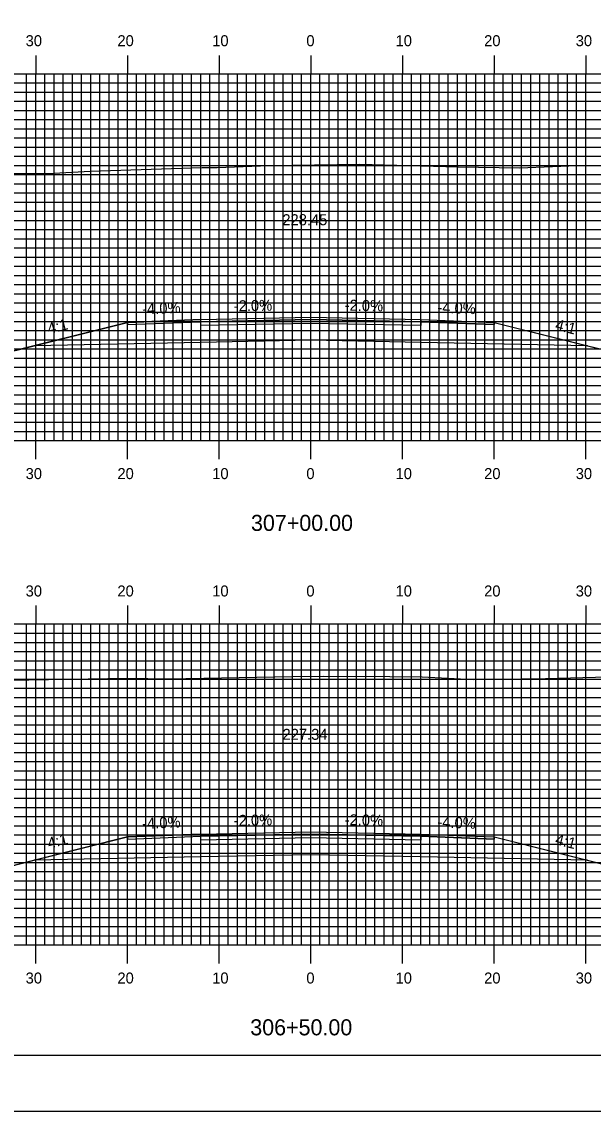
# Model space of a CAD drawing. Extents: x 1817276 to 1817620, y 442591 to 442811.
# Drawn here: x 1817410.6 to 1817472.9, y 442590.5 to 442709.3 of the extents above; entities that cross this region are included whole.
import ezdxf

# ---------------------------------------------------------------- set-up
doc = ezdxf.new("R2010")
doc.units = 0
for name, color, linetype in [('ANNOTATION', 7, 'Continuous'), ('BORDER', 7, 'Continuous'), ('D_Roadway_Centerline', 7, 'Continuous'), ('D_Roadway_Centerline_Text', 7, 'Continuous'), ('D_Roadway_Edge_Shoulder', 7, 'Continuous'), ('D_Roadway_Edge_TW', 7, 'Continuous'), ('D_Roadway_Pavement', 7, 'Continuous'), ('D_Roadway_SlopeLines', 7, 'Continuous'), ('D_Roadway_SubGrade', 7, 'Continuous'), ('H_V ANNOTATION', 7, 'Continuous'), ('MAJOR', 7, 'Continuous'), ('MINOR', 7, 'Continuous'), ('PLOT BOUNDARY', 7, 'Continuous'), ('S_Roadway_Centerline', 7, 'Continuous')]:
    doc.layers.add(name, color=color, linetype=linetype)

msp = doc.modelspace()

# ---------------------------------------------------------------- linework, layer by layer
at = {"layer": 'BORDER'}
msp.add_lwpolyline([(1817292.5, 442596.67), (1817612.5, 442596.67), (1817612.5, 442806.67), (1817292.5, 442806.67)], close=True, dxfattribs=at)
at = {"layer": 'D_Roadway_Centerline'}
for points in [[(1817352.1, 442690.39), (1817353.35, 442690.39), (1817354.6, 442690.2), (1817355.85, 442689.84), (1817357.1, 442689.31), (1817382.3, 442676.71), (1817397.29, 442676.56), (1817407.93, 442673.01), (1817411.93, 442674.01), (1817422.1, 442676.56), (1817430.1, 442676.88), (1817442.1, 442677.12), (1817454.1, 442676.88), (1817462.1, 442676.56), (1817472.27, 442674.01), (1817476.27, 442673.01), (1817486.9, 442676.56), (1817496.05, 442676.65), (1817527.1, 442692.17), (1817528.35, 442692.72), (1817529.6, 442693.1), (1817530.85, 442693.31), (1817532.1, 442693.37)], [(1817352.1, 442636.54), (1817353.35, 442636.48), (1817354.6, 442636.26), (1817355.85, 442635.88), (1817357.1, 442635.33), (1817386.65, 442620.56), (1817397.29, 442620.45), (1817407.93, 442616.91), (1817411.93, 442617.91), (1817422.1, 442620.45), (1817430.1, 442620.77), (1817442.1, 442621.01), (1817454.1, 442620.77), (1817462.1, 442620.45), (1817472.27, 442617.91), (1817476.27, 442616.91), (1817486.9, 442620.45), (1817496.1, 442620.54), (1817527.1, 442636.04), (1817528.35, 442636.58), (1817529.6, 442636.96), (1817530.85, 442637.17), (1817532.1, 442637.21)]]:
    msp.add_lwpolyline(points, dxfattribs=at)
at = {"layer": 'D_Roadway_Edge_Shoulder'}
for points in [[(1817430.1, 442676.88), (1817422.1, 442676.56), (1817422.1, 442676.31), (1817430.1, 442676.63)], [(1817454.1, 442676.88), (1817462.1, 442676.56), (1817462.1, 442676.31), (1817454.1, 442676.63)], [(1817430.1, 442620.77), (1817422.1, 442620.45), (1817422.1, 442620.2), (1817430.1, 442620.52)], [(1817454.1, 442620.77), (1817462.1, 442620.45), (1817462.1, 442620.2), (1817454.1, 442620.52)]]:
    msp.add_lwpolyline(points, close=True, dxfattribs=at)
at = {"layer": 'D_Roadway_Edge_TW'}
for points in [[(1817430.1, 442676.63), (1817430.1, 442676.88), (1817442.1, 442677.12), (1817454.1, 442676.88), (1817454.1, 442676.63), (1817442.1, 442676.87)], [(1817430.1, 442620.52), (1817430.1, 442620.77), (1817442.1, 442621.01), (1817454.1, 442620.77), (1817454.1, 442620.52), (1817442.1, 442620.76)]]:
    msp.add_lwpolyline(points, close=True, dxfattribs=at)
at = {"layer": 'D_Roadway_Pavement'}
for points in [[(1817430.1, 442676.21), (1817430.1, 442676.63), (1817442.1, 442676.87), (1817454.1, 442676.63), (1817454.1, 442676.21), (1817442.1, 442676.45)], [(1817430.1, 442620.1), (1817430.1, 442620.52), (1817442.1, 442620.76), (1817454.1, 442620.52), (1817454.1, 442620.1), (1817442.1, 442620.34)]]:
    msp.add_lwpolyline(points, close=True, dxfattribs=at)
at = {"layer": 'D_Roadway_SlopeLines'}
for points in [[(1817422.1, 442676.56), (1817407.93, 442673.01)], [(1817462.1, 442676.56), (1817476.27, 442673.01)], [(1817422.1, 442620.45), (1817407.93, 442616.91)], [(1817462.1, 442620.45), (1817476.27, 442616.91)]]:
    msp.add_lwpolyline(points, dxfattribs=at)
at = {"layer": 'D_Roadway_SubGrade'}
for points in [[(1817430.1, 442674.38), (1817411.93, 442674.01), (1817422.1, 442676.56), (1817422.1, 442676.31), (1817430.1, 442676.63), (1817442.1, 442676.87), (1817454.1, 442676.63), (1817462.1, 442676.31), (1817462.1, 442676.56), (1817472.27, 442674.01), (1817454.1, 442674.38), (1817442.1, 442674.62)], [(1817430.1, 442618.27), (1817411.93, 442617.91), (1817422.1, 442620.45), (1817422.1, 442620.2), (1817430.1, 442620.52), (1817442.1, 442620.76), (1817454.1, 442620.52), (1817462.1, 442620.2), (1817462.1, 442620.45), (1817472.27, 442617.91), (1817454.1, 442618.27), (1817442.1, 442618.51)]]:
    msp.add_lwpolyline(points, close=True, dxfattribs=at)
at = {"layer": 'MAJOR'}
for p, q in [((1817412.1, 442705.67), (1817412.1, 442703.67)), ((1817422.1, 442705.67), (1817422.1, 442703.67)), ((1817432.1, 442705.67), (1817432.1, 442703.67)), ((1817442.1, 442705.67), (1817442.1, 442703.67)), ((1817452.1, 442705.67), (1817452.1, 442703.67)), ((1817462.1, 442705.67), (1817462.1, 442703.67)), ((1817472.1, 442705.67), (1817472.1, 442703.67)), ((1817302.1, 442703.67), (1817582.1, 442703.67)), ((1817302.1, 442703.67), (1817582.1, 442703.67)), ((1817412.1, 442663.67), (1817412.1, 442703.67)), ((1817422.1, 442663.67), (1817422.1, 442703.67)), ((1817432.1, 442663.67), (1817432.1, 442703.67)), ((1817442.1, 442663.67), (1817442.1, 442703.67)), ((1817452.1, 442663.67), (1817452.1, 442703.67)), ((1817462.1, 442663.67), (1817462.1, 442703.67)), ((1817472.1, 442663.67), (1817472.1, 442703.67)), ((1817302.1, 442698.67), (1817582.1, 442698.67)), ((1817302.1, 442693.67), (1817582.1, 442693.67)), ((1817302.1, 442688.67), (1817582.1, 442688.67)), ((1817302.1, 442683.67), (1817582.1, 442683.67)), ((1817302.1, 442678.67), (1817582.1, 442678.67)), ((1817302.1, 442673.67), (1817582.1, 442673.67)), ((1817302.1, 442668.67), (1817582.1, 442668.67)), ((1817302.1, 442663.67), (1817582.1, 442663.67)), ((1817302.1, 442663.67), (1817582.1, 442663.67)), ((1817412.1, 442661.66), (1817412.1, 442663.67)), ((1817422.1, 442661.66), (1817422.1, 442663.67)), ((1817432.1, 442661.66), (1817432.1, 442663.67)), ((1817442.1, 442661.66), (1817442.1, 442663.67)), ((1817452.1, 442661.66), (1817452.1, 442663.67)), ((1817462.1, 442661.66), (1817462.1, 442663.67)), ((1817472.1, 442661.66), (1817472.1, 442663.67)), ((1817412.1, 442645.67), (1817412.1, 442643.67)), ((1817422.1, 442645.67), (1817422.1, 442643.67)), ((1817432.1, 442645.67), (1817432.1, 442643.67)), ((1817442.1, 442645.67), (1817442.1, 442643.67)), ((1817452.1, 442645.67), (1817452.1, 442643.67)), ((1817462.1, 442645.67), (1817462.1, 442643.67)), ((1817472.1, 442645.67), (1817472.1, 442643.67)), ((1817302.1, 442643.67), (1817582.1, 442643.67)), ((1817302.1, 442643.67), (1817582.1, 442643.67)), ((1817412.1, 442608.67), (1817412.1, 442643.67)), ((1817422.1, 442608.67), (1817422.1, 442643.67)), ((1817432.1, 442608.67), (1817432.1, 442643.67)), ((1817442.1, 442608.67), (1817442.1, 442643.67)), ((1817452.1, 442608.67), (1817452.1, 442643.67)), ((1817462.1, 442608.67), (1817462.1, 442643.67)), ((1817472.1, 442608.67), (1817472.1, 442643.67)), ((1817302.1, 442638.67), (1817582.1, 442638.67)), ((1817302.1, 442633.67), (1817582.1, 442633.67)), ((1817302.1, 442628.67), (1817582.1, 442628.67)), ((1817302.1, 442623.67), (1817582.1, 442623.67)), ((1817302.1, 442618.67), (1817582.1, 442618.67)), ((1817302.1, 442613.67), (1817582.1, 442613.67)), ((1817302.1, 442608.67), (1817582.1, 442608.67)), ((1817302.1, 442608.67), (1817582.1, 442608.67)), ((1817412.1, 442606.66), (1817412.1, 442608.67)), ((1817422.1, 442606.66), (1817422.1, 442608.67)), ((1817432.1, 442606.66), (1817432.1, 442608.67)), ((1817442.1, 442606.66), (1817442.1, 442608.67)), ((1817452.1, 442606.66), (1817452.1, 442608.67)), ((1817462.1, 442606.66), (1817462.1, 442608.67)), ((1817472.1, 442606.66), (1817472.1, 442608.67))]:
    msp.add_line(p, q, dxfattribs=at)
at = {"layer": 'MINOR'}
for p, q in [((1817302.1, 442702.67), (1817582.1, 442702.67)), ((1817411.1, 442663.67), (1817411.1, 442703.67)), ((1817413.1, 442663.67), (1817413.1, 442703.67)), ((1817414.1, 442663.67), (1817414.1, 442703.67)), ((1817415.1, 442663.67), (1817415.1, 442703.67)), ((1817416.1, 442663.67), (1817416.1, 442703.67)), ((1817417.1, 442663.67), (1817417.1, 442703.67)), ((1817418.1, 442663.67), (1817418.1, 442703.67)), ((1817419.1, 442663.67), (1817419.1, 442703.67)), ((1817420.1, 442663.67), (1817420.1, 442703.67)), ((1817421.1, 442663.67), (1817421.1, 442703.67)), ((1817423.1, 442663.67), (1817423.1, 442703.67)), ((1817424.1, 442663.67), (1817424.1, 442703.67)), ((1817425.1, 442663.67), (1817425.1, 442703.67)), ((1817426.1, 442663.67), (1817426.1, 442703.67)), ((1817427.1, 442663.67), (1817427.1, 442703.67)), ((1817428.1, 442663.67), (1817428.1, 442703.67)), ((1817429.1, 442663.67), (1817429.1, 442703.67)), ((1817430.1, 442663.67), (1817430.1, 442703.67)), ((1817431.1, 442663.67), (1817431.1, 442703.67)), ((1817433.1, 442663.67), (1817433.1, 442703.67)), ((1817434.1, 442663.67), (1817434.1, 442703.67)), ((1817435.1, 442663.67), (1817435.1, 442703.67)), ((1817436.1, 442663.67), (1817436.1, 442703.67)), ((1817437.1, 442663.67), (1817437.1, 442703.67)), ((1817438.1, 442663.67), (1817438.1, 442703.67)), ((1817439.1, 442663.67), (1817439.1, 442703.67)), ((1817440.1, 442663.67), (1817440.1, 442703.67)), ((1817441.1, 442663.67), (1817441.1, 442703.67)), ((1817443.1, 442663.67), (1817443.1, 442703.67)), ((1817444.1, 442663.67), (1817444.1, 442703.67)), ((1817445.1, 442663.67), (1817445.1, 442703.67)), ((1817446.1, 442663.67), (1817446.1, 442703.67)), ((1817447.1, 442663.67), (1817447.1, 442703.67)), ((1817448.1, 442663.67), (1817448.1, 442703.67)), ((1817449.1, 442663.67), (1817449.1, 442703.67)), ((1817450.1, 442663.67), (1817450.1, 442703.67)), ((1817451.1, 442663.67), (1817451.1, 442703.67)), ((1817453.1, 442663.67), (1817453.1, 442703.67)), ((1817454.1, 442663.67), (1817454.1, 442703.67)), ((1817455.1, 442663.67), (1817455.1, 442703.67)), ((1817456.1, 442663.67), (1817456.1, 442703.67)), ((1817457.1, 442663.67), (1817457.1, 442703.67)), ((1817458.1, 442663.67), (1817458.1, 442703.67)), ((1817459.1, 442663.67), (1817459.1, 442703.67)), ((1817460.1, 442663.67), (1817460.1, 442703.67)), ((1817461.1, 442663.67), (1817461.1, 442703.67)), ((1817463.1, 442663.67), (1817463.1, 442703.67)), ((1817464.1, 442663.67), (1817464.1, 442703.67)), ((1817465.1, 442663.67), (1817465.1, 442703.67)), ((1817466.1, 442663.67), (1817466.1, 442703.67)), ((1817467.1, 442663.67), (1817467.1, 442703.67)), ((1817468.1, 442663.67), (1817468.1, 442703.67)), ((1817469.1, 442663.67), (1817469.1, 442703.67)), ((1817470.1, 442663.67), (1817470.1, 442703.67)), ((1817471.1, 442663.67), (1817471.1, 442703.67)), ((1817302.1, 442701.67), (1817582.1, 442701.67)), ((1817302.1, 442700.67), (1817582.1, 442700.67)), ((1817302.1, 442699.67), (1817582.1, 442699.67)), ((1817302.1, 442697.67), (1817582.1, 442697.67)), ((1817302.1, 442696.67), (1817582.1, 442696.67)), ((1817302.1, 442695.67), (1817582.1, 442695.67)), ((1817302.1, 442694.67), (1817582.1, 442694.67)), ((1817302.1, 442692.67), (1817582.1, 442692.67)), ((1817302.1, 442691.67), (1817582.1, 442691.67)), ((1817302.1, 442690.67), (1817582.1, 442690.67)), ((1817302.1, 442689.67), (1817582.1, 442689.67)), ((1817302.1, 442687.67), (1817582.1, 442687.67)), ((1817302.1, 442686.67), (1817582.1, 442686.67)), ((1817302.1, 442685.67), (1817582.1, 442685.67)), ((1817302.1, 442684.67), (1817582.1, 442684.67)), ((1817302.1, 442682.67), (1817582.1, 442682.67)), ((1817302.1, 442681.67), (1817582.1, 442681.67)), ((1817302.1, 442680.67), (1817582.1, 442680.67)), ((1817302.1, 442679.67), (1817582.1, 442679.67)), ((1817302.1, 442677.67), (1817582.1, 442677.67)), ((1817302.1, 442676.67), (1817582.1, 442676.67)), ((1817302.1, 442675.67), (1817582.1, 442675.67)), ((1817302.1, 442674.67), (1817582.1, 442674.67)), ((1817302.1, 442672.67), (1817582.1, 442672.67)), ((1817302.1, 442671.67), (1817582.1, 442671.67)), ((1817302.1, 442670.67), (1817582.1, 442670.67)), ((1817302.1, 442669.67), (1817582.1, 442669.67)), ((1817302.1, 442667.67), (1817582.1, 442667.67)), ((1817302.1, 442666.67), (1817582.1, 442666.67)), ((1817302.1, 442665.67), (1817582.1, 442665.67)), ((1817302.1, 442664.67), (1817582.1, 442664.67)), ((1817411.1, 442608.67), (1817411.1, 442643.67)), ((1817413.1, 442608.67), (1817413.1, 442643.67)), ((1817414.1, 442608.67), (1817414.1, 442643.67)), ((1817415.1, 442608.67), (1817415.1, 442643.67)), ((1817416.1, 442608.67), (1817416.1, 442643.67)), ((1817417.1, 442608.67), (1817417.1, 442643.67)), ((1817418.1, 442608.67), (1817418.1, 442643.67)), ((1817419.1, 442608.67), (1817419.1, 442643.67)), ((1817420.1, 442608.67), (1817420.1, 442643.67)), ((1817421.1, 442608.67), (1817421.1, 442643.67)), ((1817423.1, 442608.67), (1817423.1, 442643.67)), ((1817424.1, 442608.67), (1817424.1, 442643.67)), ((1817425.1, 442608.67), (1817425.1, 442643.67)), ((1817426.1, 442608.67), (1817426.1, 442643.67)), ((1817427.1, 442608.67), (1817427.1, 442643.67)), ((1817428.1, 442608.67), (1817428.1, 442643.67)), ((1817429.1, 442608.67), (1817429.1, 442643.67)), ((1817430.1, 442608.67), (1817430.1, 442643.67)), ((1817431.1, 442608.67), (1817431.1, 442643.67)), ((1817433.1, 442608.67), (1817433.1, 442643.67)), ((1817434.1, 442608.67), (1817434.1, 442643.67)), ((1817435.1, 442608.67), (1817435.1, 442643.67)), ((1817436.1, 442608.67), (1817436.1, 442643.67)), ((1817437.1, 442608.67), (1817437.1, 442643.67)), ((1817438.1, 442608.67), (1817438.1, 442643.67)), ((1817439.1, 442608.67), (1817439.1, 442643.67)), ((1817440.1, 442608.67), (1817440.1, 442643.67)), ((1817441.1, 442608.67), (1817441.1, 442643.67)), ((1817443.1, 442608.67), (1817443.1, 442643.67)), ((1817444.1, 442608.67), (1817444.1, 442643.67)), ((1817445.1, 442608.67), (1817445.1, 442643.67)), ((1817446.1, 442608.67), (1817446.1, 442643.67)), ((1817447.1, 442608.67), (1817447.1, 442643.67)), ((1817448.1, 442608.67), (1817448.1, 442643.67)), ((1817449.1, 442608.67), (1817449.1, 442643.67)), ((1817450.1, 442608.67), (1817450.1, 442643.67)), ((1817451.1, 442608.67), (1817451.1, 442643.67)), ((1817453.1, 442608.67), (1817453.1, 442643.67)), ((1817454.1, 442608.67), (1817454.1, 442643.67)), ((1817455.1, 442608.67), (1817455.1, 442643.67)), ((1817456.1, 442608.67), (1817456.1, 442643.67)), ((1817457.1, 442608.67), (1817457.1, 442643.67)), ((1817458.1, 442608.67), (1817458.1, 442643.67)), ((1817459.1, 442608.67), (1817459.1, 442643.67)), ((1817460.1, 442608.67), (1817460.1, 442643.67)), ((1817461.1, 442608.67), (1817461.1, 442643.67)), ((1817463.1, 442608.67), (1817463.1, 442643.67)), ((1817464.1, 442608.67), (1817464.1, 442643.67)), ((1817465.1, 442608.67), (1817465.1, 442643.67)), ((1817466.1, 442608.67), (1817466.1, 442643.67)), ((1817467.1, 442608.67), (1817467.1, 442643.67)), ((1817468.1, 442608.67), (1817468.1, 442643.67)), ((1817469.1, 442608.67), (1817469.1, 442643.67)), ((1817470.1, 442608.67), (1817470.1, 442643.67)), ((1817471.1, 442608.67), (1817471.1, 442643.67)), ((1817302.1, 442642.67), (1817582.1, 442642.67)), ((1817302.1, 442641.67), (1817582.1, 442641.67)), ((1817302.1, 442640.67), (1817582.1, 442640.67)), ((1817302.1, 442639.67), (1817582.1, 442639.67)), ((1817302.1, 442637.67), (1817582.1, 442637.67)), ((1817302.1, 442636.67), (1817582.1, 442636.67)), ((1817302.1, 442635.67), (1817582.1, 442635.67)), ((1817302.1, 442634.67), (1817582.1, 442634.67)), ((1817302.1, 442632.67), (1817582.1, 442632.67)), ((1817302.1, 442631.67), (1817582.1, 442631.67)), ((1817302.1, 442630.67), (1817582.1, 442630.67)), ((1817302.1, 442629.67), (1817582.1, 442629.67)), ((1817302.1, 442627.67), (1817582.1, 442627.67)), ((1817302.1, 442626.67), (1817582.1, 442626.67)), ((1817302.1, 442625.67), (1817582.1, 442625.67)), ((1817302.1, 442624.67), (1817582.1, 442624.67)), ((1817302.1, 442622.67), (1817582.1, 442622.67)), ((1817302.1, 442621.67), (1817582.1, 442621.67)), ((1817302.1, 442620.67), (1817582.1, 442620.67)), ((1817302.1, 442619.67), (1817582.1, 442619.67)), ((1817302.1, 442617.67), (1817582.1, 442617.67)), ((1817302.1, 442616.67), (1817582.1, 442616.67)), ((1817302.1, 442615.67), (1817582.1, 442615.67)), ((1817302.1, 442614.67), (1817582.1, 442614.67)), ((1817302.1, 442612.67), (1817582.1, 442612.67)), ((1817302.1, 442611.67), (1817582.1, 442611.67)), ((1817302.1, 442610.67), (1817582.1, 442610.67)), ((1817302.1, 442609.67), (1817582.1, 442609.67))]:
    msp.add_line(p, q, dxfattribs=at)
at = {"layer": 'PLOT BOUNDARY'}
msp.add_lwpolyline([(1817276.31, 442590.55), (1817616.31, 442590.55), (1817616.31, 442810.55), (1817276.31, 442810.55)], close=True, dxfattribs=at)
at = {"layer": 'S_Roadway_Centerline'}
for points in [[(1817344.15, 442689.94), (1817353.51, 442690.47), (1817361.97, 442691.11), (1817365.72, 442691.38), (1817370.54, 442691.68), (1817377.14, 442692.08), (1817379.05, 442692.13), (1817382.17, 442692.26), (1817396.37, 442692.79), (1817404.43, 442692.76), (1817414.08, 442692.84), (1817418.03, 442693.03), (1817430.26, 442693.46), (1817431.88, 442693.45), (1817437.57, 442693.65), (1817447.47, 442693.79), (1817458.17, 442693.51), (1817464.85, 442693.41), (1817472.07, 442693.71), (1817481.2, 442693.66)], [(1817350.88, 442636.52), (1817357.89, 442636.64), (1817374.78, 442637.31), (1817375.33, 442637.33), (1817375.51, 442637.33), (1817387.71, 442636.98), (1817391.72, 442637.1), (1817402.43, 442637.7), (1817409.21, 442637.56), (1817422.1, 442637.76), (1817426.54, 442637.69), (1817440.09, 442637.94), (1817443.47, 442637.98), (1817450.71, 442637.96), (1817454.26, 442637.9), (1817459.85, 442637.62), (1817467.72, 442637.74), (1817477.24, 442637.99)]]:
    msp.add_lwpolyline(points, dxfattribs=at)

# ---------------------------------------------------------------- texts
at = {"layer": 'ANNOTATION'}
for s, rotation, p in [('-2.0%', 1.1458, (1817433.71, 442677.75)), ('-2.0%', 358.8542, (1817445.79, 442677.84)), ('-4.0%', 2.2906, (1817423.73, 442677.42)), ('-4.0%', 357.7094, (1817455.89, 442677.61)), ('4:1', 14.0362, (1817413.55, 442675.28)), ('4:1', 345.9638, (1817468.69, 442675.77)), ('-4.0%', 2.2906, (1817423.73, 442621.32)), ('-2.0%', 1.1458, (1817433.71, 442621.64)), ('-2.0%', 358.8542, (1817445.79, 442621.74)), ('-4.0%', 357.7094, (1817455.89, 442621.5)), ('4:1', 14.0362, (1817413.55, 442619.17)), ('4:1', 345.9638, (1817468.69, 442619.66))]:
    msp.add_text(s, height=1.2, rotation=rotation, dxfattribs=at).set_placement(p)
at = {"layer": 'D_Roadway_Centerline'}
for s, p in [('C', (1817442.09, 442677.12)), ('L', (1817442.1, 442677.11)), ('C', (1817442.09, 442621.01)), ('L', (1817442.1, 442621))]:
    msp.add_text(s, height=0.0146, dxfattribs=at).set_placement(p)
at = {"layer": 'D_Roadway_Centerline_Text'}
for s, p in [('228.45', (1817439, 442687.15)), ('227.34', (1817439.02, 442631.04))]:
    msp.add_text(s, height=1.2, dxfattribs=at).set_placement(p)
at = {"layer": 'H_V ANNOTATION'}
for s, height, p in [('30', 1.2, (1817411, 442706.67)), ('20', 1.2, (1817421.01, 442706.67)), ('10', 1.2, (1817431.35, 442706.67)), ('0', 1.2, (1817441.62, 442706.67)), ('10', 1.2, (1817451.35, 442706.67)), ('20', 1.2, (1817461.01, 442706.67)), ('30', 1.2, (1817471, 442706.67)), ('30', 1.2, (1817411, 442659.47)), ('20', 1.2, (1817421.01, 442659.47)), ('10', 1.2, (1817431.35, 442659.47)), ('0', 1.2, (1817441.62, 442659.47)), ('10', 1.2, (1817451.35, 442659.47)), ('20', 1.2, (1817461.01, 442659.47)), ('30', 1.2, (1817471, 442659.47)), ('307+00.00', 1.75, (1817435.58, 442653.82)), ('30', 1.2, (1817411, 442646.67)), ('20', 1.2, (1817421.01, 442646.67)), ('10', 1.2, (1817431.35, 442646.67)), ('0', 1.2, (1817441.62, 442646.67)), ('10', 1.2, (1817451.35, 442646.67)), ('20', 1.2, (1817461.01, 442646.67)), ('30', 1.2, (1817471, 442646.67)), ('30', 1.2, (1817411, 442604.47)), ('20', 1.2, (1817421.01, 442604.47)), ('10', 1.2, (1817431.35, 442604.47)), ('0', 1.2, (1817441.62, 442604.47)), ('10', 1.2, (1817451.35, 442604.47)), ('20', 1.2, (1817461.01, 442604.47)), ('30', 1.2, (1817471, 442604.47)), ('306+50.00', 1.75, (1817435.5, 442598.82))]:
    msp.add_text(s, height=height, dxfattribs=at).set_placement(p)

doc.saveas('drawing.dxf')
